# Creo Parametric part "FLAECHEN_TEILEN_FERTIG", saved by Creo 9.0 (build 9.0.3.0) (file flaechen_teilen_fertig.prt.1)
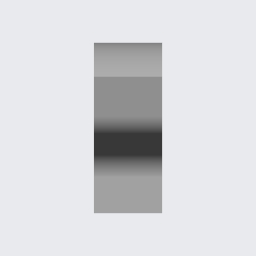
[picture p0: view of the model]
Materials in the file: S235JRG2

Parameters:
  BENENNUNG = "XXX"
  DATUM = "XX.XX.XX"
  ERSTELLER = "ARINDA"
  TEILETYP = "Fertigungsteil"
  PTC_MASTER_MATERIAL = "S235JRG2"
  SELECT_EN_NAME = "S235JRG2"
  SELECT_DIN_NAME = "RSt37-2"
  SELECT_DIN_NUMBER = "1.0038"
  SELECT_ASTM_NAME = "A 283 M Grade 2"
  MATERIAL_GROUP = "ME_ST_Baustahl"
  STANDARD_EN_DELIVERYSPEC = "DIN EN 10025"
  STANDARD_DIN_DELIVERYSPEC = "DIN 17100"

Other parameters: MASSE

Created from: ARINDA-STARTTEIL.PRT

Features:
  1. coordinate system "CS0"
  2. datum plane "DTM1", "T_RECHTS_Y-Z"
  3. datum plane "DTM2", "T_OBEN_X-Z"
  4. datum plane "DTM3", "T_VORNE_X-Y"
  5. datum axis "T_X-ACHSE"
  6. datum axis "A_1"
  7. datum axis "A_2"
  8. extrusion "Profil 1"
  9. extruded cut "Profil 2"
  10. round "Rundung 1"
  11. feature "Fläche Teilen 1"

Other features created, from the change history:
  feature "Kopieren 1"
  feature "Flächenbereich Trennen 1"
  feature "Fläche Teilen 1"
  feature "Versatz 1"
  feature "Versatz 2"
  revolve "Drehen 1"

Other named items: T_BASIC, T_Y-ACHSE, T_Z-ACHSE

Layers: 00_STD-ACHSEN, 00_STD-EBENEN, 00_STD-KOORDSYS, 01_ACHSEN, FLAECHEN, SAMMELFLÄCHEN, VOLUMENGEOMETRIE

Surfaces: 10 tabulated cylinder, 8 plane, 4 cylinder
